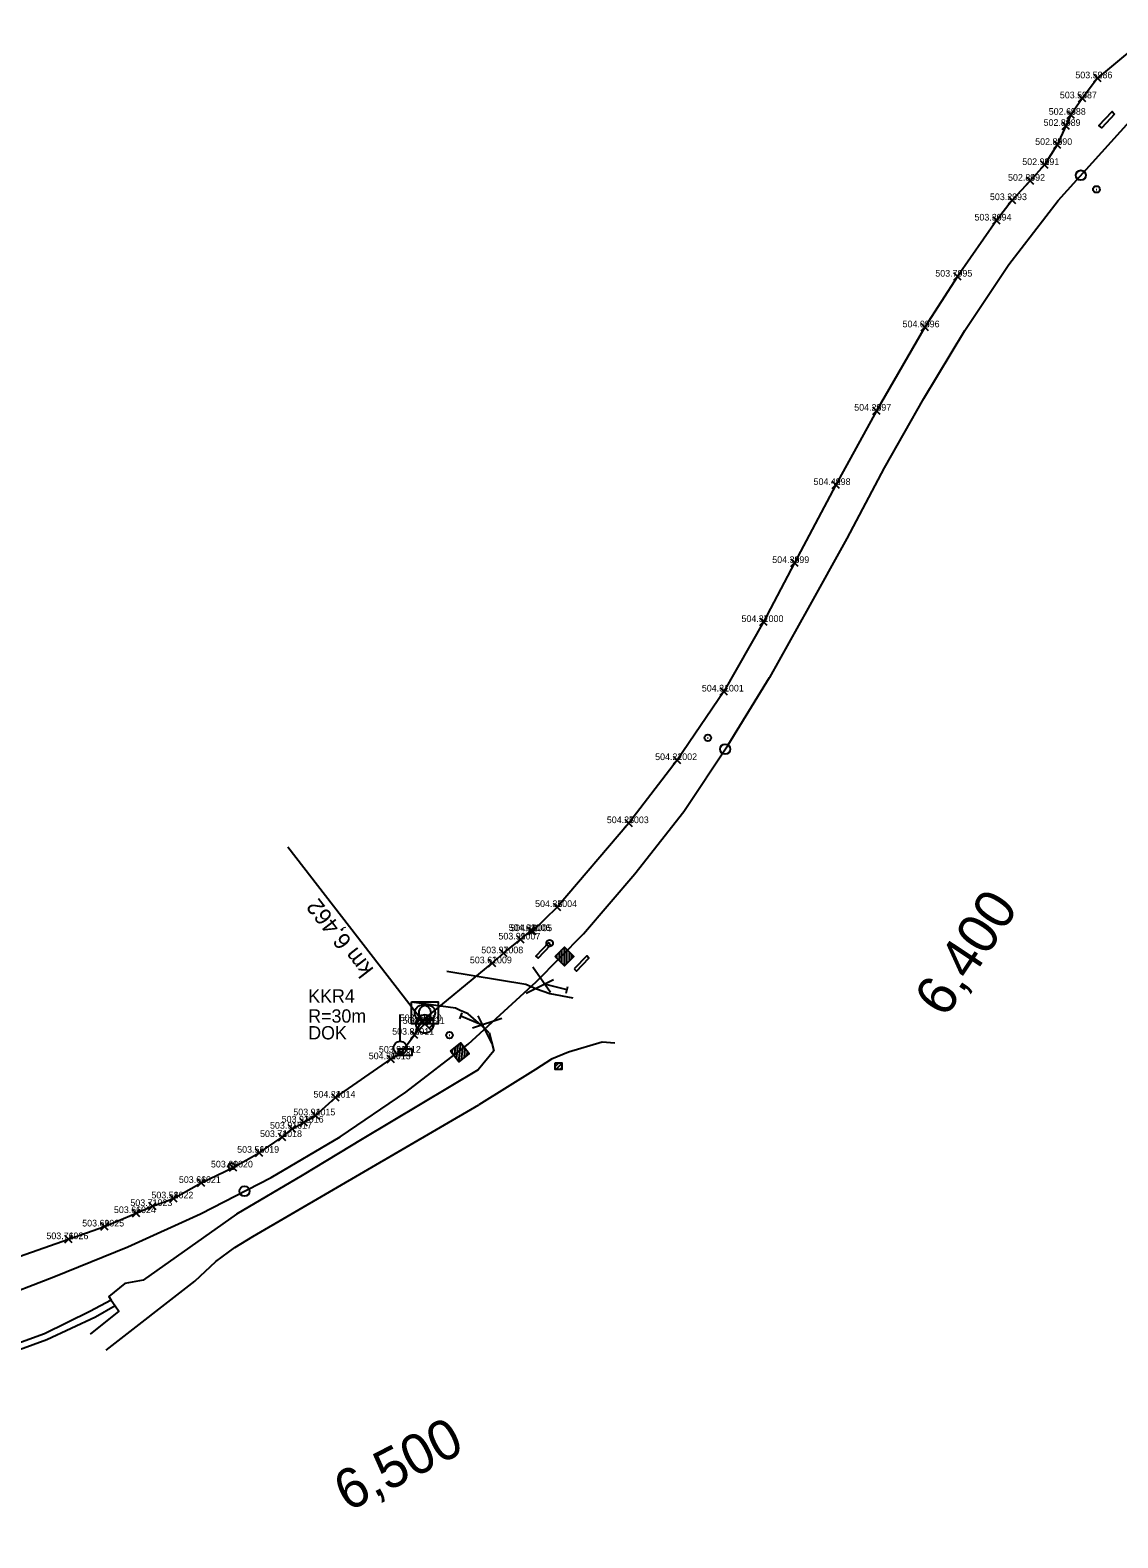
# Model space of a CAD drawing. Extents: x -874058 to -854960, y -10531873 to -1049126.
# Drawn here: x -870333.3 to -870169.8, y -1054293.1 to -1054066.4 of the extents above; entities that cross this region are included whole.
import ezdxf

# ---------------------------------------------------------------- set-up
doc = ezdxf.new("R2010")
doc.units = 0
for name, color, linetype in [('Vrstva 1', 7, 'Continuous'), ('Vrstva 18', 7, 'Continuous'), ('Vrstva 25', 7, 'Continuous'), ('Vrstva 3', 7, 'Continuous'), ('Vrstva 31', 7, 'Continuous'), ('Vrstva 32', 7, 'Continuous'), ('Vrstva 35', 7, 'Continuous'), ('Vrstva 36', 7, 'Continuous'), ('Vrstva 37', 7, 'Continuous'), ('Vrstva 4', 7, 'Continuous'), ('Vrstva 50', 7, 'Continuous'), ('Vrstva 51', 7, 'Continuous'), ('Vrstva 60', 7, 'Continuous'), ('Vrstva 61', 7, 'Continuous'), ('Vrstva 7', 7, 'Continuous')]:
    doc.layers.add(name, color=color, linetype=linetype)

msp = doc.modelspace()

# ---------------------------------------------------------------- linework, layer by layer
at = {"layer": 'Vrstva 1'}
msp.add_lwpolyline([(-870338.81, -1054257.38), (-870329.71, -1054253.85), (-870318.57, -1054249.32), (-870307.65, -1054244.38), (-870297.05, -1054238.91), (-870286.7, -1054232.83), (-870276.79, -1054226.1), (-870267.42, -1054218.86), (-870257.2, -1054209.5), (-870250.12, -1054202.3), (-870242.37, -1054193.27), (-870235.02, -1054183.89), (-870228.37, -1054173.86), (-870222.14, -1054163.75), (-870222.09, -1054163.74), (-870216.27, -1054153.32), (-870210.46, -1054142.85), (-870204.85, -1054132.23), (-870198.96, -1054121.81), (-870192.81, -1054111.59), (-870186.17, -1054101.65), (-870178.76, -1054092.03), (-870162.85, -1054074.39)], dxfattribs=at)
at = {"layer": 'Vrstva 18'}
for points in [[(-870170.29, -1054079.07), (-870172.21, -1054081.1), (-870172.63, -1054080.75), (-870170.67, -1054078.69), (-870170.29, -1054079.07)], [(-870255.05, -1054203.97), (-870255.37, -1054203.63), (-870257.28, -1054205.63), (-870256.94, -1054205.95), (-870255.05, -1054203.97)], [(-870251.49, -1054207.57), (-870251.15, -1054207.89), (-870249.3, -1054205.93), (-870249.62, -1054205.59), (-870251.49, -1054207.57)]]:
    msp.add_lwpolyline(points, dxfattribs=at)
at = {"layer": 'Vrstva 25'}
msp.add_lwpolyline([(-870277.89, -1054220.59), (-870277.89, -1054219.59), (-870275.89, -1054219.59), (-870275.89, -1054220.59), (-870277.89, -1054220.59)], dxfattribs=at)
at = {"layer": 'Vrstva 3'}
for p, q in [((-870254.09, -1054205.99), (-870254.09, -1054205.41)), ((-870253.72, -1054206.36), (-870253.71, -1054205.03)), ((-870253.34, -1054206.74), (-870253.34, -1054204.66)), ((-870252.97, -1054207.11), (-870252.96, -1054204.28)), ((-870252.59, -1054206.74), (-870252.59, -1054204.66)), ((-870252.22, -1054206.37), (-870252.21, -1054205.04)), ((-870251.84, -1054205.99), (-870251.84, -1054205.41)), ((-870269.5, -1054220.68), (-870269.36, -1054219.36)), ((-870269.17, -1054221.09), (-870268.94, -1054219.03)), ((-870268.84, -1054221.51), (-870268.53, -1054218.69)), ((-870268.43, -1054221.17), (-870268.2, -1054219.11)), ((-870269.83, -1054220.26), (-870269.77, -1054219.69)), ((-870268.01, -1054220.84), (-870267.87, -1054219.52)), ((-870267.6, -1054220.51), (-870267.53, -1054219.94))]:
    msp.add_line(p, q, dxfattribs=at)
for points in [[(-870254.38, -1054205.7), (-870252.96, -1054204.28), (-870251.55, -1054205.7), (-870252.97, -1054207.11)], [(-870254.38, -1054205.7), (-870252.96, -1054204.28), (-870251.55, -1054205.7), (-870252.97, -1054207.11)], [(-870270.09, -1054219.95), (-870268.53, -1054218.69), (-870267.28, -1054220.26), (-870268.84, -1054221.51)], [(-870270.09, -1054219.95), (-870268.53, -1054218.69), (-870267.28, -1054220.26), (-870268.84, -1054221.51)]]:
    msp.add_lwpolyline(points, close=True, dxfattribs=at)
for points in [[(-870254.38, -1054205.7), (-870252.96, -1054204.28), (-870251.55, -1054205.7), (-870252.97, -1054207.11), (-870254.38, -1054205.7)], [(-870254.38, -1054205.7), (-870252.96, -1054204.28), (-870251.55, -1054205.7), (-870252.97, -1054207.11), (-870254.38, -1054205.7)], [(-870270.09, -1054219.95), (-870268.53, -1054218.69), (-870267.28, -1054220.26), (-870268.84, -1054221.51), (-870270.09, -1054219.95)], [(-870270.09, -1054219.95), (-870268.53, -1054218.69), (-870267.28, -1054220.26), (-870268.84, -1054221.51), (-870270.09, -1054219.95)]]:
    msp.add_lwpolyline(points, dxfattribs=at)
at = {"layer": 'Vrstva 31'}
for p, q in [((-870273, -1054214.87), (-870273, -1054214.87)), ((-870273, -1054214.87), (-870273, -1054214.87)), ((-870275.31, -1054215.83), (-870274.63, -1054215.16)), ((-870275.14, -1054216.48), (-870274.23, -1054215.56)), ((-870274.92, -1054216.78), (-870274.92, -1054216.78)), ((-870274.92, -1054216.78), (-870274.92, -1054216.78)), ((-870273.73, -1054216.05), (-870272.81, -1054215.13)), ((-870273.32, -1054216.46), (-870272.61, -1054215.75)), ((-870272.99, -1054216.78), (-870272.99, -1054216.78))]:
    msp.add_line(p, q, dxfattribs=at)
for points in [[(-870274.91, -1054214.87), (-870273.96, -1054215.83), (-870274.92, -1054216.78)], [(-870273, -1054214.87), (-870273.95, -1054215.83), (-870272.99, -1054216.78)]]:
    msp.add_lwpolyline(points, dxfattribs=at)
for centre, start, end in [((-870273.96, -1054215.83), 134.5239, 224.7609), ((-870273.95, -1054215.83), 45.4761, 134.8422), ((-870273.95, -1054215.83), 315.2391, 45.4761), ((-870273.96, -1054215.83), 224.7623, 315.5517)]:
    msp.add_arc(centre, 1.35, start, end, dxfattribs=at)
at = {"layer": 'Vrstva 32'}
msp.add_line((-870274.03, -1054213.01), (-870273.98, -1054213.02), dxfattribs=at)
for points in [[(-870164.2, -1054066.44), (-870172.85, -1054073.68), (-870175.18, -1054076.69), (-870176.85, -1054079.16), (-870177.63, -1054080.83), (-870178.89, -1054083.69), (-870180.83, -1054086.71), (-870182.97, -1054089.08), (-870185.69, -1054091.99), (-870188.01, -1054095.06), (-870193.9, -1054103.49), (-870198.82, -1054111.11), (-870206.09, -1054123.65), (-870212.2, -1054134.81), (-870218.41, -1054146.54), (-870223.03, -1054155.41), (-870228.99, -1054165.86), (-870236.01, -1054176.17), (-870243.27, -1054185.65), (-870254.05, -1054198.26), (-870257.79, -1054201.89)], [(-870274.4, -1054215.41), (-870263.85, -1054206.72), (-870262.14, -1054205.21), (-870259.56, -1054203.14), (-870258.02, -1054201.86), (-870257.79, -1054201.89)], [(-870338.67, -1054252.12), (-870327.5, -1054248.19), (-870322.12, -1054246.28), (-870317.35, -1054244.27), (-870314.88, -1054243.21), (-870311.72, -1054242.06), (-870307.59, -1054239.73), (-870302.77, -1054237.41), (-870298.83, -1054235.2), (-870295.39, -1054232.84), (-870293.89, -1054231.58), (-870292.14, -1054230.66), (-870290.39, -1054229.58), (-870287.36, -1054226.91), (-870279.05, -1054221.14), (-870277.53, -1054220.15), (-870275.53, -1054217.46), (-870274.4, -1054215.41)]]:
    msp.add_lwpolyline(points, dxfattribs=at)
msp.add_lwpolyline([(-870275.94, -1054212.51), (-870271.96, -1054212.51), (-870271.96, -1054215.83), (-870275.94, -1054215.83)], close=True, dxfattribs=at)
for centre in [(-870274.27, -1054214.18), (-870273.61, -1054214.15)]:
    msp.add_circle(centre, 1.2, dxfattribs=at)
at = {"layer": 'Vrstva 35'}
msp.add_lwpolyline([(-870277.53, -1054220.15), (-870275.53, -1054217.46), (-870274.4, -1054215.41), (-870263.85, -1054206.72), (-870262.14, -1054205.21), (-870259.56, -1054203.14)], dxfattribs=at)
at = {"layer": 'Vrstva 36'}
for p, q in [((-870254.36, -1054222.24), (-870253.81, -1054221.69)), ((-870254.25, -1054222.69), (-870253.36, -1054221.8)), ((-870253.68, -1054222.69), (-870253.36, -1054222.37))]:
    msp.add_line(p, q, dxfattribs=at)
msp.add_lwpolyline([(-870254.36, -1054221.69), (-870253.36, -1054221.69), (-870253.36, -1054222.69), (-870254.36, -1054222.69), (-870254.36, -1054221.69)], dxfattribs=at)
at = {"layer": 'Vrstva 37'}
for p, q in [((-870277.65, -1054218.43), (-870277.65, -1054214.43)), ((-870277.65, -1054219.43), (-870277.65, -1054219.43))]:
    msp.add_line(p, q, dxfattribs=at)
msp.add_circle((-870277.65, -1054219.43), 1, dxfattribs=at)
at = {"layer": 'Vrstva 4'}
for p, q in [((-870255.09, -1054211.1), (-870257.74, -1054207.32)), ((-870258.73, -1054211.2), (-870254.6, -1054209.16)), ((-870252.57, -1054210.71), (-870255.96, -1054209.84)), ((-870252.69, -1054211.19), (-870252.45, -1054210.23)), ((-870268.37, -1054214.17), (-870268.75, -1054215.09)), ((-870268.56, -1054214.63), (-870265.33, -1054215.98)), ((-870266.01, -1054214.61), (-870263.93, -1054218.73)), ((-870262.39, -1054215.04), (-870266.78, -1054216.46))]:
    msp.add_line(p, q, dxfattribs=at)
at = {"layer": 'Vrstva 50'}
for p, q in [((-870255.24, -1054203.69), (-870255.14, -1054203.69)), ((-870270.29, -1054217.51), (-870270.19, -1054217.51))]:
    msp.add_line(p, q, dxfattribs=at)
for centre in [(-870255.19, -1054203.69), (-870270.24, -1054217.51)]:
    msp.add_circle(centre, 0.5, dxfattribs=at)
at = {"layer": 'Vrstva 51'}
for points in [[(-870270.66, -1054207.91), (-870258.79, -1054209.88), (-870257.15, -1054210.57), (-870255.15, -1054211.27), (-870251.72, -1054211.9)], [(-870264.3, -1054217.16), (-870265.48, -1054216.01), (-870267.46, -1054214.3), (-870268.64, -1054213.8), (-870269.32, -1054213.47), (-870275.95, -1054212.57)], [(-870264.3, -1054217.16), (-870263.59, -1054219.86), (-870265.93, -1054222.75), (-870283.35, -1054233.18), (-870292.37, -1054238.61), (-870302.24, -1054244.44), (-870316.29, -1054254.37), (-870319.03, -1054254.83), (-870321.46, -1054256.79), (-870321.09, -1054257.37), (-870320.49, -1054258.19), (-870319.96, -1054259), (-870324.27, -1054262.45)], [(-870245.39, -1054218.71), (-870247.3, -1054218.6), (-870252.38, -1054220.09), (-870254.9, -1054221.13), (-870257.33, -1054222.67), (-870265.82, -1054228.01)], [(-870321.86, -1054264.86), (-870308.52, -1054254.49), (-870305.35, -1054251.57), (-870302.5, -1054249.43), (-870299.78, -1054247.81), (-870265.82, -1054228.01)], [(-870321.09, -1054257.37), (-870324.31, -1054259.08), (-870331.14, -1054262.4), (-870347.59, -1054268.39), (-870365.9, -1054275.88), (-870388.82, -1054285.22), (-870405.47, -1054292.01)], [(-870323.44, -1054259.94), (-870330.75, -1054263.32), (-870347.23, -1054269.32), (-870365.52, -1054276.8), (-870388.44, -1054286.14), (-870405.47, -1054293.09)], [(-870320.49, -1054258.19), (-870323.44, -1054259.94)]]:
    msp.add_lwpolyline(points, dxfattribs=at)
at = {"layer": 'Vrstva 60'}
for p, q in [((-870173.4, -1054074.23), (-870172.3, -1054073.13)), ((-870172.3, -1054074.23), (-870173.4, -1054073.13)), ((-870175.73, -1054077.24), (-870174.63, -1054076.14)), ((-870174.63, -1054077.24), (-870175.73, -1054076.14)), ((-870177.4, -1054079.71), (-870176.3, -1054078.61)), ((-870176.3, -1054079.71), (-870177.4, -1054078.61)), ((-870178.18, -1054081.38), (-870177.08, -1054080.28)), ((-870177.08, -1054081.38), (-870178.18, -1054080.28)), ((-870179.44, -1054084.24), (-870178.34, -1054083.14)), ((-870178.34, -1054084.24), (-870179.44, -1054083.14)), ((-870181.38, -1054087.26), (-870180.28, -1054086.16)), ((-870180.28, -1054087.26), (-870181.38, -1054086.16)), ((-870183.52, -1054089.63), (-870182.42, -1054088.53)), ((-870182.42, -1054089.63), (-870183.52, -1054088.53)), ((-870186.24, -1054092.54), (-870185.14, -1054091.44)), ((-870185.14, -1054092.54), (-870186.24, -1054091.44)), ((-870188.56, -1054095.61), (-870187.46, -1054094.51)), ((-870187.46, -1054095.61), (-870188.56, -1054094.51)), ((-870194.45, -1054104.04), (-870193.35, -1054102.94)), ((-870193.35, -1054104.04), (-870194.45, -1054102.94)), ((-870199.37, -1054111.66), (-870198.27, -1054110.56)), ((-870198.27, -1054111.66), (-870199.37, -1054110.56)), ((-870206.64, -1054124.2), (-870205.54, -1054123.1)), ((-870205.54, -1054124.2), (-870206.64, -1054123.1)), ((-870212.75, -1054135.36), (-870211.65, -1054134.26)), ((-870211.65, -1054135.36), (-870212.75, -1054134.26)), ((-870218.96, -1054147.09), (-870217.86, -1054145.99)), ((-870217.86, -1054147.09), (-870218.96, -1054145.99)), ((-870223.58, -1054155.96), (-870222.48, -1054154.86)), ((-870222.48, -1054155.96), (-870223.58, -1054154.86)), ((-870229.54, -1054166.41), (-870228.44, -1054165.31)), ((-870228.44, -1054166.41), (-870229.54, -1054165.31)), ((-870236.56, -1054176.72), (-870235.46, -1054175.62)), ((-870235.46, -1054176.72), (-870236.56, -1054175.62)), ((-870243.82, -1054186.2), (-870242.72, -1054185.1)), ((-870242.72, -1054186.2), (-870243.82, -1054185.1)), ((-870254.6, -1054198.81), (-870253.5, -1054197.71)), ((-870253.5, -1054198.81), (-870254.6, -1054197.71)), ((-870260.11, -1054203.69), (-870259.01, -1054202.59)), ((-870259.01, -1054203.69), (-870260.11, -1054202.59)), ((-870258.57, -1054202.41), (-870257.47, -1054201.31)), ((-870257.47, -1054202.41), (-870258.57, -1054201.31)), ((-870258.34, -1054202.44), (-870257.24, -1054201.34)), ((-870257.24, -1054202.44), (-870258.34, -1054201.34)), ((-870262.69, -1054205.76), (-870261.59, -1054204.66)), ((-870261.59, -1054205.76), (-870262.69, -1054204.66)), ((-870264.4, -1054207.27), (-870263.3, -1054206.17)), ((-870263.3, -1054207.27), (-870264.4, -1054206.17)), ((-870274.95, -1054215.96), (-870273.85, -1054214.86)), ((-870273.85, -1054215.96), (-870274.95, -1054214.86)), ((-870276.08, -1054218.01), (-870274.98, -1054216.91)), ((-870274.98, -1054218.01), (-870276.08, -1054216.91)), ((-870274.5, -1054216.38), (-870273.4, -1054215.28)), ((-870273.4, -1054216.38), (-870274.5, -1054215.28)), ((-870279.6, -1054221.69), (-870278.5, -1054220.59)), ((-870278.5, -1054221.69), (-870279.6, -1054220.59)), ((-870278.08, -1054220.7), (-870276.98, -1054219.6)), ((-870276.98, -1054220.7), (-870278.08, -1054219.6)), ((-870287.91, -1054227.46), (-870286.81, -1054226.36)), ((-870286.81, -1054227.46), (-870287.91, -1054226.36)), ((-870292.69, -1054231.21), (-870291.59, -1054230.11)), ((-870291.59, -1054231.21), (-870292.69, -1054230.11)), ((-870290.94, -1054230.13), (-870289.84, -1054229.03)), ((-870289.84, -1054230.13), (-870290.94, -1054229.03)), ((-870295.94, -1054233.39), (-870294.84, -1054232.29)), ((-870294.84, -1054233.39), (-870295.94, -1054232.29)), ((-870294.44, -1054232.13), (-870293.34, -1054231.03)), ((-870293.34, -1054232.13), (-870294.44, -1054231.03)), ((-870299.38, -1054235.75), (-870298.28, -1054234.65)), ((-870298.28, -1054235.75), (-870299.38, -1054234.65)), ((-870303.32, -1054237.96), (-870302.22, -1054236.86)), ((-870302.22, -1054237.96), (-870303.32, -1054236.86)), ((-870308.14, -1054240.28), (-870307.04, -1054239.18)), ((-870307.04, -1054240.28), (-870308.14, -1054239.18)), ((-870312.27, -1054242.61), (-870311.17, -1054241.51)), ((-870311.17, -1054242.61), (-870312.27, -1054241.51)), ((-870317.9, -1054244.82), (-870316.8, -1054243.72)), ((-870316.8, -1054244.82), (-870317.9, -1054243.72)), ((-870315.43, -1054243.76), (-870314.33, -1054242.66)), ((-870314.33, -1054243.76), (-870315.43, -1054242.66)), ((-870322.67, -1054246.83), (-870321.57, -1054245.73)), ((-870321.57, -1054246.83), (-870322.67, -1054245.73)), ((-870328.05, -1054248.74), (-870326.95, -1054247.64)), ((-870326.95, -1054248.74), (-870328.05, -1054247.64))]:
    msp.add_line(p, q, dxfattribs=at)
at = {"layer": 'Vrstva 7'}
for p, q in [((-870173.07, -1054090.37), (-870172.97, -1054090.37)), ((-870231.46, -1054172.81), (-870231.36, -1054172.81)), ((-870294.54, -1054189.19), (-870273.95, -1054215.83)), ((-870303.05, -1054237.23), (-870302.95, -1054237.23))]:
    msp.add_line(p, q, dxfattribs=at)
for centre, radius in [((-870175.36, -1054088.26), 0.75), ((-870173.02, -1054090.37), 0.5), ((-870231.41, -1054172.81), 0.5), ((-870228.81, -1054174.53), 0.75), ((-870303, -1054237.23), 0.5), ((-870301.06, -1054240.98), 0.75)]:
    msp.add_circle(centre, radius, dxfattribs=at)

# ---------------------------------------------------------------- texts
at = {"layer": 'Vrstva 32'}
for s, p in [('KKR4', (-870291.47, -1054212.63)), ('R=30m', (-870291.47, -1054215.64)), ('DOK', (-870291.47, -1054218.16))]:
    msp.add_text(s, height=2, dxfattribs=at).set_placement(p)
at = {"layer": 'Vrstva 60'}
for s, p in [('986', (-870172.85, -1054073.68)), ('987', (-870175.18, -1054076.69)), ('988', (-870176.85, -1054079.16)), ('989', (-870177.63, -1054080.83)), ('990', (-870178.89, -1054083.69)), ('991', (-870180.83, -1054086.71)), ('992', (-870182.97, -1054089.08)), ('993', (-870185.69, -1054091.99)), ('994', (-870188.01, -1054095.06)), ('995', (-870193.9, -1054103.49)), ('996', (-870198.82, -1054111.11)), ('997', (-870206.09, -1054123.65)), ('998', (-870212.2, -1054134.81)), ('999', (-870218.41, -1054146.54)), ('1000', (-870223.03, -1054155.41)), ('1001', (-870228.99, -1054165.86)), ('1002', (-870236.01, -1054176.17)), ('1003', (-870243.27, -1054185.65)), ('1004', (-870254.05, -1054198.26)), ('1006', (-870258.02, -1054201.86)), ('1005', (-870257.79, -1054201.89)), ('1007', (-870259.56, -1054203.14)), ('1009', (-870263.85, -1054206.72)), ('1008', (-870262.14, -1054205.21)), ('1010', (-870274.4, -1054215.41)), ('1821', (-870273.95, -1054215.83)), ('1011', (-870275.53, -1054217.46)), ('1012', (-870277.53, -1054220.15)), ('1013', (-870279.05, -1054221.14)), ('1014', (-870287.36, -1054226.91)), ('1017', (-870293.89, -1054231.58)), ('1016', (-870292.14, -1054230.66)), ('1015', (-870290.39, -1054229.58)), ('1018', (-870295.39, -1054232.84)), ('1019', (-870298.83, -1054235.2)), ('1020', (-870302.77, -1054237.41)), ('1021', (-870307.59, -1054239.73)), ('1022', (-870311.72, -1054242.06)), ('1024', (-870317.35, -1054244.27)), ('1023', (-870314.88, -1054243.21)), ('1025', (-870322.12, -1054246.28)), ('1026', (-870327.5, -1054248.19))]:
    msp.add_text(s, height=1, dxfattribs=at).set_placement(p)
at = {"layer": 'Vrstva 61'}
for s, p in [('503.52 ', (-870176.18, -1054073.68)), ('503.53 ', (-870178.51, -1054076.69)), ('502.63 ', (-870180.18, -1054079.16)), ('502.89 ', (-870180.96, -1054080.83)), ('502.85 ', (-870182.22, -1054083.69)), ('502.91 ', (-870184.16, -1054086.71)), ('502.84 ', (-870186.3, -1054089.08)), ('503.23 ', (-870189.02, -1054091.99)), ('503.30 ', (-870191.34, -1054095.06)), ('503.79 ', (-870197.23, -1054103.49)), ('504.03 ', (-870202.15, -1054111.11)), ('504.28 ', (-870209.42, -1054123.65)), ('504.42 ', (-870215.53, -1054134.81)), ('504.38 ', (-870221.74, -1054146.54)), ('504.37 ', (-870226.36, -1054155.41)), ('504.31 ', (-870232.32, -1054165.86)), ('504.22 ', (-870239.34, -1054176.17)), ('504.25 ', (-870246.6, -1054185.65)), ('504.35 ', (-870257.38, -1054198.26)), ('504.08 ', (-870261.35, -1054201.86)), ('504.14 ', (-870261.12, -1054201.89)), ('503.99 ', (-870262.89, -1054203.14)), ('503.62 ', (-870267.18, -1054206.72)), ('503.97 ', (-870265.47, -1054205.21)), ('503.32 ', (-870277.73, -1054215.41)), ('504.34 ', (-870277.28, -1054215.83)), ('503.88 ', (-870278.86, -1054217.46)), ('503.96 ', (-870280.86, -1054220.15)), ('504.30 ', (-870282.38, -1054221.14)), ('504.24 ', (-870290.69, -1054226.91)), ('503.91 ', (-870297.22, -1054231.58)), ('503.92 ', (-870295.47, -1054230.66)), ('503.94 ', (-870293.72, -1054229.58)), ('503.74 ', (-870298.72, -1054232.84)), ('503.56 ', (-870302.16, -1054235.2)), ('503.60 ', (-870306.1, -1054237.41)), ('503.66 ', (-870310.92, -1054239.73)), ('503.58 ', (-870315.05, -1054242.06)), ('503.66 ', (-870320.68, -1054244.27)), ('503.71 ', (-870318.21, -1054243.21)), ('503.69 ', (-870325.45, -1054246.28)), ('503.76 ', (-870330.83, -1054248.19))]:
    msp.add_text(s, height=1, dxfattribs=at).set_placement(p)
at = {"layer": 'Vrstva 7'}
for s, height, rotation, p in [('6,400', 6, 56.4552, (-870195.72, -1054215.1)), ('km 6,462', 2.5, 127.6925, (-870281.54, -1054207.64)), ('6,500', 6, 27.2955, (-870285.55, -1054289.24))]:
    msp.add_text(s, height=height, rotation=rotation, dxfattribs=at).set_placement(p)

doc.saveas('drawing.dxf')
